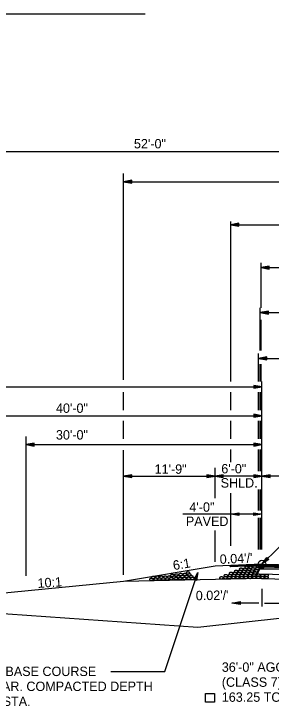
# Model space of a CAD drawing. Extents: x 1734743 to 1735935, y 759845 to 763831.
# Drawn here: x 1735766 to 1735798.9, y 763383.4 to 763471.7 of the extents above; entities that cross this region are included whole.
import ezdxf

# ---------------------------------------------------------------- set-up
doc = ezdxf.new("R2010")
doc.units = 0
for name, color, linetype in [('1', 7, 'Continuous'), ('10', 7, 'Continuous'), ('19', 7, 'Continuous'), ('8', 7, 'Continuous'), ('Level 1', 7, 'Continuous'), ('R_Prop Surface', 7, 'Continuous')]:
    doc.layers.add(name, color=color, linetype=linetype)

# ---------------------------------------------------------------- blocks, each defined once
blk = doc.blocks.new('TM')
at = {"layer": '8'}
for p, q in [((-120.309, 21.181), (-119.787, -20.829)), ((0, 0), (-120.309, 21.181)), ((-31.382, 2.945), (-120.176, 10.512)), ((-119.787, -20.829), (0, 0)), ((-119.911, -10.826), (-31.307, -3.057))]:
    blk.add_line(p, q, dxfattribs=at)
blk = doc.blocks.new('ROCKS')
at = {"layer": '1'}
blk.add_spline([(0.013, 0.06), (0.053, 0.053), (0.107, 0.033), (0.133, 0.013), (0.133, -0.007), (0.12, -0.033), (0.107, -0.04), (0.073, -0.053), (0.033, -0.067), (0.013, -0.067), (-0.02, -0.06), (-0.06, -0.053), (-0.087, -0.047), (-0.113, -0.02), (-0.113, -0.007), (-0.107, 0.02), (-0.087, 0.033), (-0.067, 0.047), (-0.033, 0.053), (-0.02, 0.06), (0.013, 0.06)], degree=3, dxfattribs=at)

msp = doc.modelspace()

# ---------------------------------------------------------------- linework, layer by layer
at = {"layer": '10'}
msp.add_lwpolyline([(1735791.622, 763385.033), (1735791.622, 763383.908), (1735790.497, 763383.908), (1735790.497, 763385.033)], close=True, dxfattribs=at)
at = {"layer": '19'}
for p, q in [((1735723.158, 763471.723), (1735782.795, 763471.723)), ((1735809.701, 763454.103), (1735757.701, 763454.103)), ((1735780.014, 763425.044), (1735780.014, 763451.355)), ((1735781.064, 763450.493), (1735780.014, 763450.309)), ((1735781.064, 763450.396), (1735780.294, 763450.335)), ((1735781.064, 763450.125), (1735781.064, 763450.493)), ((1735780.014, 763450.309), (1735851.385, 763450.309)), ((1735780.014, 763450.309), (1735781.064, 763450.125)), ((1735780.294, 763450.283), (1735781.064, 763450.213)), ((1735793.704, 763424.802), (1735793.704, 763445.228)), ((1735794.754, 763445.007), (1735793.704, 763444.824)), ((1735793.704, 763444.824), (1735794.754, 763444.64)), ((1735793.704, 763444.824), (1735839.701, 763444.824)), ((1735794.754, 763444.911), (1735793.984, 763444.85)), ((1735793.984, 763444.798), (1735794.754, 763444.727)), ((1735794.754, 763444.64), (1735794.754, 763445.007)), ((1735797.582, 763434.213), (1735797.582, 763439.954)), ((1735798.632, 763439.531), (1735797.582, 763439.347)), ((1735797.582, 763439.347), (1735833.82, 763439.347)), ((1735797.582, 763439.347), (1735798.632, 763439.164)), ((1735798.632, 763439.435), (1735797.862, 763439.374)), ((1735797.862, 763439.321), (1735798.632, 763439.251)), ((1735798.632, 763439.164), (1735798.632, 763439.531)), ((1735797.478, 763428.772), (1735797.478, 763434.213)), ((1735798.528, 763433.79), (1735797.478, 763433.607)), ((1735797.478, 763433.607), (1735833.82, 763433.607)), ((1735797.478, 763433.607), (1735798.528, 763433.423)), ((1735798.528, 763433.694), (1735797.758, 763433.633)), ((1735798.528, 763433.423), (1735798.528, 763433.79)), ((1735797.758, 763433.58), (1735798.528, 763433.51)), ((1735797.582, 763428.772), (1735797.582, 763432.7)), ((1735797.249, 763424.802), (1735797.249, 763428.374)), ((1735798.299, 763427.951), (1735797.249, 763427.768)), ((1735797.249, 763427.768), (1735834.153, 763427.768)), ((1735797.249, 763427.768), (1735798.299, 763427.584)), ((1735798.299, 763427.855), (1735797.529, 763427.794)), ((1735797.529, 763427.741), (1735798.299, 763427.671)), ((1735798.299, 763427.584), (1735798.299, 763427.951)), ((1735797.478, 763424.802), (1735797.478, 763427.033)), ((1735797.582, 763424.802), (1735797.582, 763427.033)), ((1735797.701, 763416.77), (1735797.701, 763424.802)), ((1735717.701, 763424.143), (1735797.701, 763424.143)), ((1735796.651, 763424.327), (1735796.651, 763423.959)), ((1735797.701, 763424.143), (1735796.651, 763424.327)), ((1735797.421, 763424.169), (1735796.651, 763424.231)), ((1735796.651, 763423.959), (1735797.701, 763424.143)), ((1735796.651, 763424.047), (1735797.421, 763424.117)), ((1735780.014, 763421.178), (1735780.014, 763423.445)), ((1735793.704, 763421.178), (1735793.704, 763423.445)), ((1735797.249, 763421.178), (1735797.249, 763423.445)), ((1735797.478, 763421.178), (1735797.478, 763423.445)), ((1735797.582, 763421.178), (1735797.582, 763423.445)), ((1735757.701, 763420.456), (1735797.701, 763420.456)), ((1735796.651, 763420.64), (1735796.651, 763420.273)), ((1735797.701, 763420.456), (1735796.651, 763420.64)), ((1735797.421, 763420.483), (1735796.651, 763420.544)), ((1735796.651, 763420.273), (1735797.701, 763420.456)), ((1735796.651, 763420.36), (1735797.421, 763420.43)), ((1735780.014, 763417.489), (1735780.014, 763419.821)), ((1735793.704, 763417.489), (1735793.704, 763419.821)), ((1735797.249, 763417.489), (1735797.249, 763419.821)), ((1735797.478, 763417.489), (1735797.478, 763419.821)), ((1735797.582, 763417.489), (1735797.582, 763419.821)), ((1735767.576, 763400.014), (1735767.576, 763417.816)), ((1735768.626, 763416.953), (1735767.576, 763416.77)), ((1735768.626, 763416.857), (1735767.856, 763416.796)), ((1735768.626, 763416.586), (1735768.626, 763416.953)), ((1735796.651, 763416.953), (1735796.651, 763416.586)), ((1735797.701, 763416.77), (1735796.651, 763416.953)), ((1735797.421, 763416.796), (1735796.651, 763416.857)), ((1735767.576, 763416.77), (1735768.626, 763416.586)), ((1735767.576, 763416.77), (1735797.701, 763416.77)), ((1735767.856, 763416.743), (1735768.626, 763416.673)), ((1735780.019, 763400.144), (1735780.019, 763416.057)), ((1735793.704, 763414.546), (1735793.704, 763416.132)), ((1735796.651, 763416.586), (1735797.701, 763416.77)), ((1735796.651, 763416.673), (1735797.421, 763416.743)), ((1735797.249, 763413.386), (1735797.249, 763416.132)), ((1735797.478, 763413.386), (1735797.478, 763416.132)), ((1735797.582, 763413.386), (1735797.582, 763416.132)), ((1735797.701, 763403.391), (1735797.701, 763416.77)), ((1735791.701, 763409.928), (1735791.701, 763413.803)), ((1735781.069, 763412.937), (1735780.019, 763412.753)), ((1735780.019, 763412.753), (1735791.701, 763412.753)), ((1735780.019, 763412.753), (1735781.069, 763412.569)), ((1735781.069, 763412.84), (1735780.299, 763412.779)), ((1735780.299, 763412.727), (1735781.069, 763412.657)), ((1735781.069, 763412.569), (1735781.069, 763412.937)), ((1735790.651, 763412.937), (1735790.651, 763412.569)), ((1735791.701, 763412.753), (1735790.651, 763412.937)), ((1735791.421, 763412.779), (1735790.651, 763412.84)), ((1735790.651, 763412.569), (1735791.701, 763412.753)), ((1735790.651, 763412.657), (1735791.421, 763412.727)), ((1735792.751, 763412.937), (1735791.701, 763412.753)), ((1735797.701, 763412.753), (1735791.701, 763412.753)), ((1735791.701, 763412.753), (1735792.751, 763412.569)), ((1735792.751, 763412.84), (1735791.981, 763412.779)), ((1735791.981, 763412.727), (1735792.751, 763412.657)), ((1735792.751, 763412.569), (1735792.751, 763412.937)), ((1735796.651, 763412.937), (1735796.651, 763412.569)), ((1735797.701, 763412.753), (1735796.651, 763412.937)), ((1735797.421, 763412.779), (1735796.651, 763412.84)), ((1735796.651, 763412.569), (1735797.701, 763412.753)), ((1735796.651, 763412.657), (1735797.421, 763412.727)), ((1735798.751, 763412.937), (1735797.701, 763412.753)), ((1735809.701, 763412.753), (1735797.701, 763412.753)), ((1735797.701, 763412.753), (1735798.751, 763412.569)), ((1735798.751, 763412.84), (1735797.981, 763412.779)), ((1735797.981, 763412.727), (1735798.751, 763412.657)), ((1735798.751, 763412.569), (1735798.751, 763412.937)), ((1735797.249, 763408.352), (1735797.249, 763411.061)), ((1735797.478, 763408.352), (1735797.478, 763411.061)), ((1735797.582, 763408.352), (1735797.582, 763411.061)), ((1735793.704, 763403.862), (1735793.704, 763410.568)), ((1735793.704, 763407.892), (1735794.754, 763408.075)), ((1735794.754, 763408.075), (1735794.754, 763407.708)), ((1735796.651, 763407.708), (1735796.651, 763408.075)), ((1735796.651, 763408.075), (1735797.701, 763407.892)), ((1735797.701, 763407.892), (1735787.594, 763407.892)), ((1735794.754, 763407.708), (1735793.704, 763407.892)), ((1735793.984, 763407.918), (1735794.754, 763407.979)), ((1735794.754, 763407.795), (1735793.984, 763407.865)), ((1735796.651, 763407.979), (1735797.421, 763407.918)), ((1735797.701, 763407.892), (1735796.651, 763407.708)), ((1735797.421, 763407.865), (1735796.651, 763407.795)), ((1735797.249, 763403.391), (1735797.249, 763407.438)), ((1735797.478, 763403.391), (1735797.478, 763407.438)), ((1735797.582, 763403.391), (1735797.582, 763407.438)), ((1735791.701, 763401.8), (1735791.701, 763405.829)), ((1735797.701, 763401.515), (1735798.322, 763402.381)), ((1735798.576, 763402.118), (1735797.701, 763401.515)), ((1735797.885, 763401.725), (1735798.383, 763402.311)), ((1735798.515, 763402.18), (1735797.92, 763401.69)), ((1735798.322, 763402.381), (1735798.576, 763402.118)), ((1735791.701, 763401.275), (1735780.017, 763399.328)), ((1735797.701, 763401.515), (1735791.701, 763401.275)), ((1735797.701, 763401.348), (1735793.619, 763401.185)), ((1735797.412, 763400.937), (1735797.082, 763400.277)), ((1735797.536, 763401.185), (1735797.412, 763400.937)), ((1735797.412, 763400.937), (1735833.996, 763400.205)), ((1735797.412, 763400.937), (1735833.996, 763400.205)), ((1735833.996, 763400.205), (1735797.412, 763400.937)), ((1735797.536, 763401.185), (1735833.869, 763400.458)), ((1735833.869, 763400.458), (1735797.536, 763401.185)), ((1735797.701, 763401.515), (1735833.701, 763400.795)), ((1735797.701, 763401.348), (1735833.701, 763400.628)), ((1735785.305, 763387.849), (1735789.51, 763400.474)), ((1735789.006, 763399.538), (1735789.51, 763400.474)), ((1735789.088, 763399.511), (1735789.395, 763400.219)), ((1735789.442, 763400.203), (1735789.265, 763399.454)), ((1735789.51, 763400.474), (1735789.351, 763399.42)), ((1735797.082, 763400.277), (1735834.332, 763399.532)), ((1735797.082, 763400.277), (1735834.332, 763399.532)), ((1735780.015, 763399.327), (1735757.701, 763397.096)), ((1735795.701, 763399.641), (1735780.017, 763399.328)), ((1735789.351, 763399.42), (1735789.006, 763399.538)), ((1735797.701, 763399.681), (1735795.701, 763399.641)), ((1735797.701, 763399.681), (1735835.7, 763398.921)), ((1735797.664, 763398.38), (1735797.664, 763396.127)), ((1735797.285, 763396.543), (1735793.864, 763396.543)), ((1735798.043, 763396.543), (1735801.464, 763396.543)), ((1735800.684, 763394.688), (1735789.496, 763393.421)), ((1735778.402, 763387.849), (1735785.305, 763387.849))]:
    msp.add_line(p, q, dxfattribs=at)
for points in [[(1735806.283, 763407.626), (1735803.928, 763407.626), (1735797.701, 763401.515)], [(1735833.701, 763400.628), (1735797.701, 763401.348), (1735797.616, 763401.345), (1735793.619, 763401.185), (1735793.619, 763401.185), (1735793.704, 763401.355), (1735793.704, 763401.355), (1735797.701, 763401.515), (1735833.701, 763400.795), (1735839.701, 763400.555), (1735839.701, 763400.555), (1735839.786, 763400.385), (1735833.701, 763400.628), (1735833.701, 763400.628), (1735833.701, 763400.628)], [(1735833.869, 763400.458), (1735797.536, 763401.185), (1735797.536, 763401.185), (1735797.616, 763401.345), (1735797.616, 763401.345), (1735797.701, 763401.348), (1735833.377, 763400.634), (1735833.786, 763400.625), (1735833.786, 763400.625), (1735833.869, 763400.458), (1735833.869, 763400.458), (1735833.869, 763400.458)], [(1735789.496, 763393.421), (1735765.245, 763395.158), (1735755.142, 763395.49)]]:
    msp.add_lwpolyline(points, dxfattribs=at)
msp.add_circle((1735797.701, 763401.515), 0.5, dxfattribs=at)
at = {"layer": 'R_Prop Surface'}
for p, q in [((1735793.704, 763401.355), (1735793.619, 763401.185)), ((1735797.616, 763401.345), (1735797.082, 763400.277))]:
    msp.add_line(p, q, dxfattribs=at)

# ---------------------------------------------------------------- block references
at = {"layer": '19', "xscale": 0.008761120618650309, "yscale": -0.008761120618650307, "rotation": -179.20057588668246}
msp.add_blockref('TM', (1735793.861, 763396.539), dxfattribs=at)
at = {"layer": 'Level 1', "xscale": 2.011654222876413}
for p, yscale, rotation in [((1735795.014, 763400.877), 2.0116542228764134, 2.041282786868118), ((1735795.52, 763400.888), 2.0116542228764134, 2.041282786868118), ((1735795.717, 763401.133), 2.0116542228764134, 2.041282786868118), ((1735796.037, 763400.886), 2.0116542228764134, 2.041282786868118), ((1735796.228, 763401.133), 2.0116542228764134, 2.041282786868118), ((1735796.557, 763400.917), 2.0116542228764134, 2.041282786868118), ((1735796.744, 763401.163), 2.0116542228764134, 2.041282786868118), ((1735797.098, 763400.972), 2.0116542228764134, 2.041282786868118), ((1735797.265, 763401.206), 2.0116542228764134, 2.041282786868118), ((1735786.22, 763400.087), 2.011654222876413, 1.8263814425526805), ((1735786.773, 763400.135), 2.011654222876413, 1.8263814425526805), ((1735786.991, 763399.92), 2.011654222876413, 1.8263814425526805), ((1735787.306, 763400.194), 2.011654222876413, 1.8263814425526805), ((1735787.525, 763399.94), 2.011654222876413, 1.8263814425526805), ((1735787.832, 763400.208), 2.011654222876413, 1.8263814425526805), ((1735788.056, 763399.965), 2.011654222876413, 1.8263814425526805), ((1735788.234, 763400.401), 2.011654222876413, 1.8263814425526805), ((1735788.407, 763400.161), 2.011654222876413, 1.8263814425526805), ((1735788.639, 763399.935), 2.011654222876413, 1.8263814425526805), ((1735793.07, 763400.055), 2.0116542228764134, 2.041282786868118), ((1735793.586, 763400.081), 2.0116542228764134, 2.041282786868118), ((1735793.716, 763400.344), 2.0116542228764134, 2.041282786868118), ((1735794.09, 763400.091), 2.0116542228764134, 2.041282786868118), ((1735794.229, 763400.35), 2.0116542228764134, 2.041282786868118), ((1735794.372, 763400.6), 2.0116542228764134, 2.041282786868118), ((1735794.596, 763400.101), 2.0116542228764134, 2.041282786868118), ((1735794.738, 763400.368), 2.0116542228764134, 2.041282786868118), ((1735794.883, 763400.618), 2.0116542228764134, 2.041282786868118), ((1735795.105, 763400.101), 2.0116542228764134, 2.041282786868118), ((1735795.247, 763400.362), 2.0116542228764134, 2.041282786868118), ((1735795.392, 763400.621), 2.0116542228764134, 2.041282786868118), ((1735795.627, 763400.113), 2.0116542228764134, 2.041282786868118), ((1735795.766, 763400.379), 2.0116542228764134, 2.041282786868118), ((1735795.912, 763400.635), 2.0116542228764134, 2.041282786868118), ((1735796.16, 763400.098), 2.0116542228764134, 2.041282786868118), ((1735796.281, 763400.361), 2.0116542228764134, 2.041282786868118), ((1735796.418, 763400.645), 2.0116542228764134, 2.041282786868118), ((1735796.694, 763400.117), 2.0116542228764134, 2.041282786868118), ((1735796.823, 763400.402), 2.0116542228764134, 2.041282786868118), ((1735796.97, 763400.68), 2.0116542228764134, 2.041282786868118), ((1735797.229, 763400.119), 2.0116542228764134, 2.041282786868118), ((1735797.753, 763400.093), 2.0116542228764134, 2.041282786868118), ((1735798.271, 763400.09), 2.0116542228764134, 2.041282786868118), ((1735783.569, 763399.59), 2.011654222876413, 1.8263814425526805), ((1735783.789, 763399.827), 2.011654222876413, 1.8263814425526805), ((1735784.098, 763399.62), 2.011654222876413, 1.8263814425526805), ((1735784.314, 763399.867), 2.011654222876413, 1.8263814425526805), ((1735784.598, 763399.634), 2.011654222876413, 1.8263814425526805), ((1735784.826, 763399.867), 2.011654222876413, 1.8263814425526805), ((1735785.094, 763399.644), 2.011654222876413, 1.8263814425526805), ((1735785.336, 763399.867), 2.011654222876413, 1.8263814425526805), ((1735785.59, 763399.652), 2.011654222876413, 1.8263814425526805), ((1735785.829, 763399.873), 2.011654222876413, 1.8263814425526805), ((1735786.081, 763399.668), 2.011654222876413, 1.8263814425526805), ((1735786.437, 763399.873), 2.011654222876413, 1.8263814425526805), ((1735786.689, 763399.668), 2.011654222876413, 1.8263814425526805), ((1735787.242, 763399.715), 2.011654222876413, 1.8263814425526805), ((1735787.782, 763399.703), 2.011654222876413, 1.8263814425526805), ((1735788.319, 763399.727), 2.011654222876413, 1.8263814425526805), ((1735788.815, 763399.69), 2.011654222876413, 1.8263814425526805), ((1735792.5, 763399.779), 2.0116542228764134, 2.041282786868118), ((1735793.014, 763399.79), 2.0116542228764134, 2.041282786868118), ((1735793.53, 763399.806), 2.0116542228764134, 2.041282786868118), ((1735794.05, 763399.822), 2.0116542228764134, 2.041282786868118), ((1735794.568, 763399.817), 2.0116542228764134, 2.041282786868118), ((1735795.105, 763399.825), 2.0116542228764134, 2.041282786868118), ((1735795.628, 763399.842), 2.0116542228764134, 2.041282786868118), ((1735796.161, 763399.836), 2.0116542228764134, 2.041282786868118), ((1735796.695, 763399.852), 2.0116542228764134, 2.041282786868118), ((1735797.231, 763399.863), 2.0116542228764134, 2.041282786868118), ((1735797.749, 763399.823), 2.0116542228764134, 2.041282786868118), ((1735798.267, 763399.826), 2.0116542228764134, 2.041282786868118)]:
    msp.add_blockref('ROCKS', p, dxfattribs=dict(at, yscale=yscale, rotation=rotation))

# ---------------------------------------------------------------- texts
at = {"layer": '19'}
for s, p in [('52\'-0"', (1735781.347, 763454.559)), ('40\'-0"', (1735771.388, 763420.821)), ('30\'-0"', (1735771.388, 763417.416)), ('11\'-9"', (1735783.987, 763413.05)), ('6\'-0"', (1735792.501, 763413.101)), ('SHLD.', (1735792.421, 763411.289)), ('4\'-0"', (1735788.433, 763408.208)), ('PAVED', (1735787.979, 763406.396))]:
    msp.add_text(s, height=1.2, dxfattribs=at).set_placement(p)
for s, rotation, p in [("0.04'/'", 2.61133, (1735792.331, 763401.546)), ('6:1', 9.45113, (1735786.431, 763400.754)), ('10:1', 3.80903, (1735769.08, 763398.483)), ("0.02'/'", 1.0121, (1735789.258, 763396.911)), ('36\'-0" AGGREGATE BASE COURSE', 360, (1735792.569, 763387.787)), ('AGGREGATE BASE COURSE', 360, (1735754.328, 763387.249)), ('(CLASS 7) - 7" COMPACTED DEPTH', 360, (1735792.569, 763385.875)), ('(CLASS 7) - VAR. COMPACTED DEPTH', 360, (1735754.328, 763385.337)), ('163.25 TONS/STA.', 360, (1735792.569, 763383.963)), ('155.50 TONS/STA.', 360, (1735754.328, 763383.425))]:
    msp.add_text(s, height=1.2, rotation=rotation, dxfattribs=at).set_placement(p)

doc.saveas('drawing.dxf')
